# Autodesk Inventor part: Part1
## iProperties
Shininess: 64.0
Length Units: 11269
Angle Units: 11279
Time Units: 11290
Mass Units: 11283
Length Display Precision: 3
Angle Display Precision: 2
Compacted: True
Part Number: Part1
Document SubType Name: Modeling
Created: 2006-07
Designer: Gilberto Alvarez M
Manufacturer: Standard
Standards Organization: Custom
Density: 0.0
Volumn: 0.0
Area: 0.0
PropertySet Name: Model Information
Control State: 0
Master: False
Checked Out: False
Author: Gilberto Alvarez M
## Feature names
1. Coil1
2. Extrusion1
